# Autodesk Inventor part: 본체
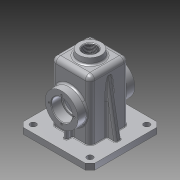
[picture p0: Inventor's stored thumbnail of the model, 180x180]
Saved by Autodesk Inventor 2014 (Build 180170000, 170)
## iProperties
Created: 2017-08
Part Number: 본체
Material: 알루미늄 6061
Document SubType Name: Modeling
Designer: user
Density: 2.71 g/cm^3
Appearance: 알루미늄 - 평지
Mass: 792.957 g
Surface Area: 898.892 cm^2
Volume: 292.604 cm^3
Author: user
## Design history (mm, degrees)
sketch "스케치1"
  geometry: L1 (-32.5, -32.5)-(32.5, -32.5); L2 (32.5, -32.5)-(32.5, 32.5); L3 (32.5, 32.5)-(-32.5, 32.5); L4 (-32.5, 32.5)-(-32.5, -32.5); L5 (-32.5, -32.5)-(32.5, 32.5); L6 (32.5, -32.5)-(-32.5, 32.5); 1 further point
  constraints: 12 end point, 2 midpoint, 2 parallel, 1 horizontal, 1 perpendicular
  dimensions: "d0" = 65 distance of L2.end L3.end; "d1" = 65 distance of L1.end L2.end (= d0)
extrude "돌출1" new body sketch "스케치1" distance "d2" = 100; taper "d3" = 0 deg
fillet "모깎기1" dims "d4" = 8
fillet "모깎기2" dims "d5" = 8
feature "쉘1" dims "d6" = 5
sketch "스케치2"
  geometry: C1 r 20 at (0, 0); 1 further point
  constraints: 1 centre point, 1 coincident
  dimensions: "d7" = 40 diameter of C1
extrude "돌출2" join sketch "스케치2" distance "d8" = 10; taper "d9" = -7 deg
sketch "스케치3"
  geometry: L1 (24.5, -27.5)-(-24.5, -27.5) reference; L2 (-27.5, -24.5)-(-27.5, 24.5) reference; L3 (-24.5, 27.5)-(24.5, 27.5) reference; L4 (27.5, 24.5)-(27.5, -24.5) reference; L5 (-60, -60)-(60, -60); L6 (60, -60)-(60, 60); L7 (60, 60)-(-60, 60); L8 (-60, 60)-(-60, -60); L9 (-60, -60)-(60, 60); L10 (60, -60)-(-60, 60); A1 r 3 centre (24.5, -24.5) between (24.5, -27.5) and (27.5, -24.5) reference; A2 r 3 centre (-24.5, -24.5) between (-27.5, -24.5) and (-24.5, -27.5) reference; A3 r 3 centre (-24.5, 24.5) between (-24.5, 27.5) and (-27.5, 24.5) reference; A4 r 3 centre (24.5, 24.5) between (27.5, 24.5) and (24.5, 27.5) reference; 1 further point
  constraints: 12 end point, 2 midpoint, 2 parallel, 1 horizontal, 1 perpendicular
  dimensions: "d10" = 120 distance of L6.end L7.end; "d11" = 120 distance of L5.end L6.end (= d10)
extrude "돌출3" join sketch "스케치3" distance "d12" = 10; taper "d13" = 0 deg
sketch "스케치4"
  geometry: L1 (-60, 0)-(60, 0) reference; L2 (-60, 0)-(-60, -10) reference; L3 (-32.5, 0)-(-32.5, 92) reference; L4 (-32.5, 87.905)-(-48, 0); 1 further point
  constraints: 2 end point, 2 point on line
  dimensions: "d16" = 12 distance of L4.end L1.start; "d17" = 10 deg angle of L4 L2
feature "리브1" sketch "스케치4" dims "d18" = 1, "d19" = 10, "d20" = 0, "d21" = 0, "d22" = 1, "d23" = 1
sketch "스케치5"
  geometry: L1 (60, 60)-(60, -60) reference; L2 (-60, 60)-(60, 60) reference; 2 further points
  dimensions: "d24" = 12.5 distance from line of L1 point (47.5, 47.5); "d25" = 12.5 distance from line of L2 point (47.5, 47.5)
hole "구멍1" sketch "스케치5" at (47.5, 47.5) diameter "d26" = 10; stored, may be unused: countersink angle "d30" = 90 deg, drill point angle "d32" = 118 deg; dims "d27" = 6, "d28" = 4, "d29" = 2, "d31" = 8
sketch "스케치6"
  geometry: L1 (84.5, -102)-(-35.5, -102) reference; L2 (84.5, -92)-(-35.5, -92) reference; C1 r 27.5 at (24.5, -47); 2 further points
  constraints: 1 centre point, 1 midpoint, 1 vertical alignment
  dimensions: "d33" = 55 diameter of C1; "d34" = 55 distance from line of L1 C1.centre
extrude "돌출4" join sketch "스케치6" distance "d35" = 15; taper "d36" = 0 deg
sketch "스케치7"
  geometry: L1 (-24.5, -32.5)-(24.5, -32.5) reference; L2 (-3, -42.5)-(3, -42.5); L3 (3, -42.5)-(3, -32.5); L4 (3, -32.5)-(-3, -32.5); L5 (-3, -32.5)-(-3, -42.5); L6 (-3, -42.5)-(3, -32.5); L7 (3, -42.5)-(-3, -32.5); 3 further points
  constraints: 12 end point, 3 midpoint, 2 parallel, 1 horizontal, 1 perpendicular, 1 point on line, 1 vertical alignment
  dimensions: "d37" = 6 distance of L2.start L2.end; "d38" = 10 distance of L2.end L3.end
extrude "돌출5" join sketch "스케치7" stored distance "d39" = 15; taper "d40" = 0 deg
hole "구멍2" diameter "d43" = 22.835; stored, may be unused: countersink angle "d47" = 90 deg, drill point angle "d49" = 118 deg; dims "d41" = 10, "d42" = 10, "d44" = 20, "d45" = 4, "d46" = 2, "d48" = 8
hole "구멍3" diameter "d52" = 30; stored, may be unused: countersink angle "d56" = 90 deg, drill point angle "d58" = 118 deg; dims "d50" = 10, "d51" = 10, "d53" = 20, "d54" = 35, "d55" = 17, "d57" = 8
chamfer "모따기1" distance "d65" = 8; stored, may be unused: second distance "d66" = 2, angle "d67" = 45 deg
fillet "모깎기3" dims "d68" = 3
fillet "모깎기4" dims "d69" = 3
fillet "모깎기5" dims "d70" = 1
fillet "모깎기6" dims "d71" = 3
sketch "스케치8"
  geometry: C1 r 17.5 at (0, 0) reference; 2 further points
  constraints: 1 vertical alignment
  dimensions: "d72" = 21 distance of point (0, 21) C1.centre
hole "구멍4" sketch "스케치8" at (0, 21) diameter "d73" = 3.242; stored, may be unused: countersink angle "d77" = 90 deg, drill point angle "d79" = 118 deg; dims "d74" = 8, "d75" = 35, "d76" = 17, "d78" = 10
fillet "모깎기7" dims "d83" = 0.3
sketch "스케치9"
  geometry: L1 (43.272, -18)-(5.728, -18) reference; L2 (57, 0)-(57, 91) reference; 2 further points
  constraints: 1 other
  dimensions: "d84" = 26 distance from line of L1 point (24.5, 8); "d85" = 32.5 distance from line of point (24.5, 8) L2
feature "엠보싱1" sketch "스케치9" dims "d0" = 65, "d1" = 65 (= d0), "d86" = 0.5, "d87" = 0
chamfer "모따기2" distance "d88" = 1; stored, may be unused: second distance "d89" = 2, angle "d90" = 45 deg
chamfer "모따기3" distance "d91" = 1; stored, may be unused: second distance "d92" = 2, angle "d93" = 45 deg
chamfer "모따기4" distance "d94" = 1; stored, may be unused: second distance "d95" = 2, angle "d96" = 45 deg
node "솔리드1"
mirror "대칭1"
mirror "대칭2"
mirror "대칭3"
pattern_linear "직사각형 패턴1" dims "d61" = 95, "d64" = 95
pattern_circular "원형 패턴1" dims angle "d81" = 360 deg
mirror "대칭4"
